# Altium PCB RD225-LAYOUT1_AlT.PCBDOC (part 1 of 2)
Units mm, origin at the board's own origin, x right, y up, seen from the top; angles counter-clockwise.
Board outline 85.6 x 53.98 mm, 2 copper layers (TOP, BOTTOM), stack 0 mm thick; 16 components, 11 nets, 48 pads, 0 vias.
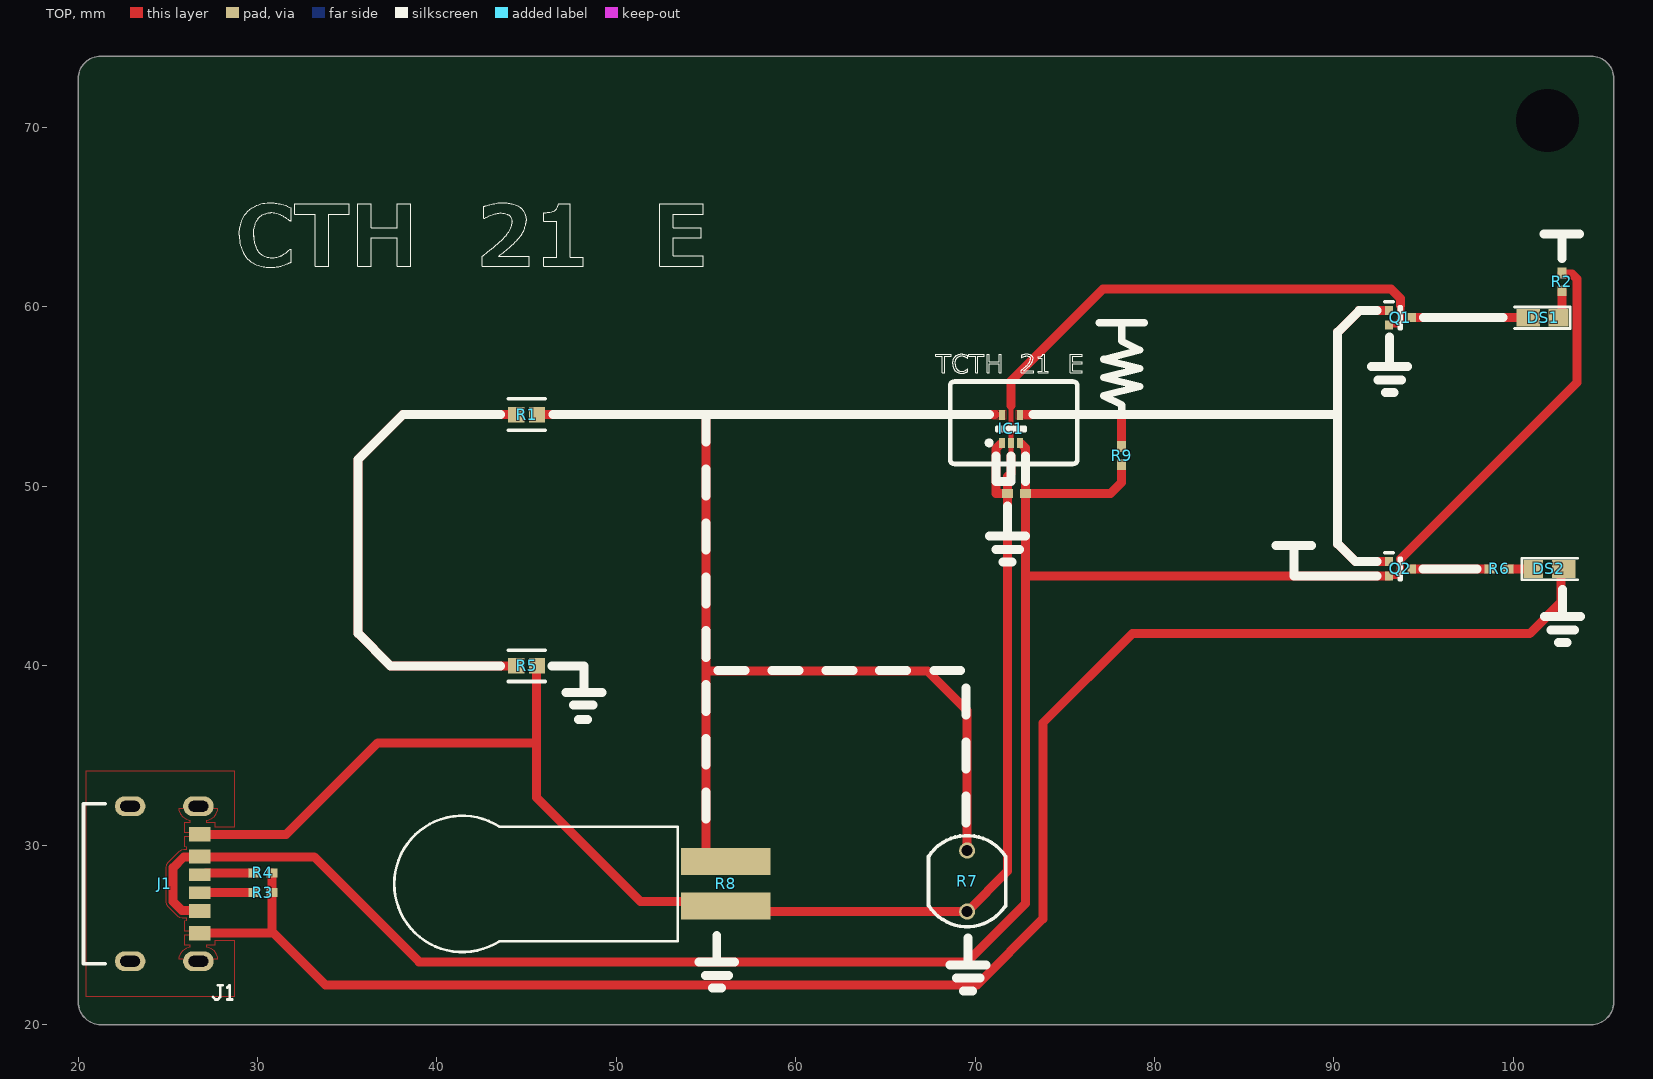
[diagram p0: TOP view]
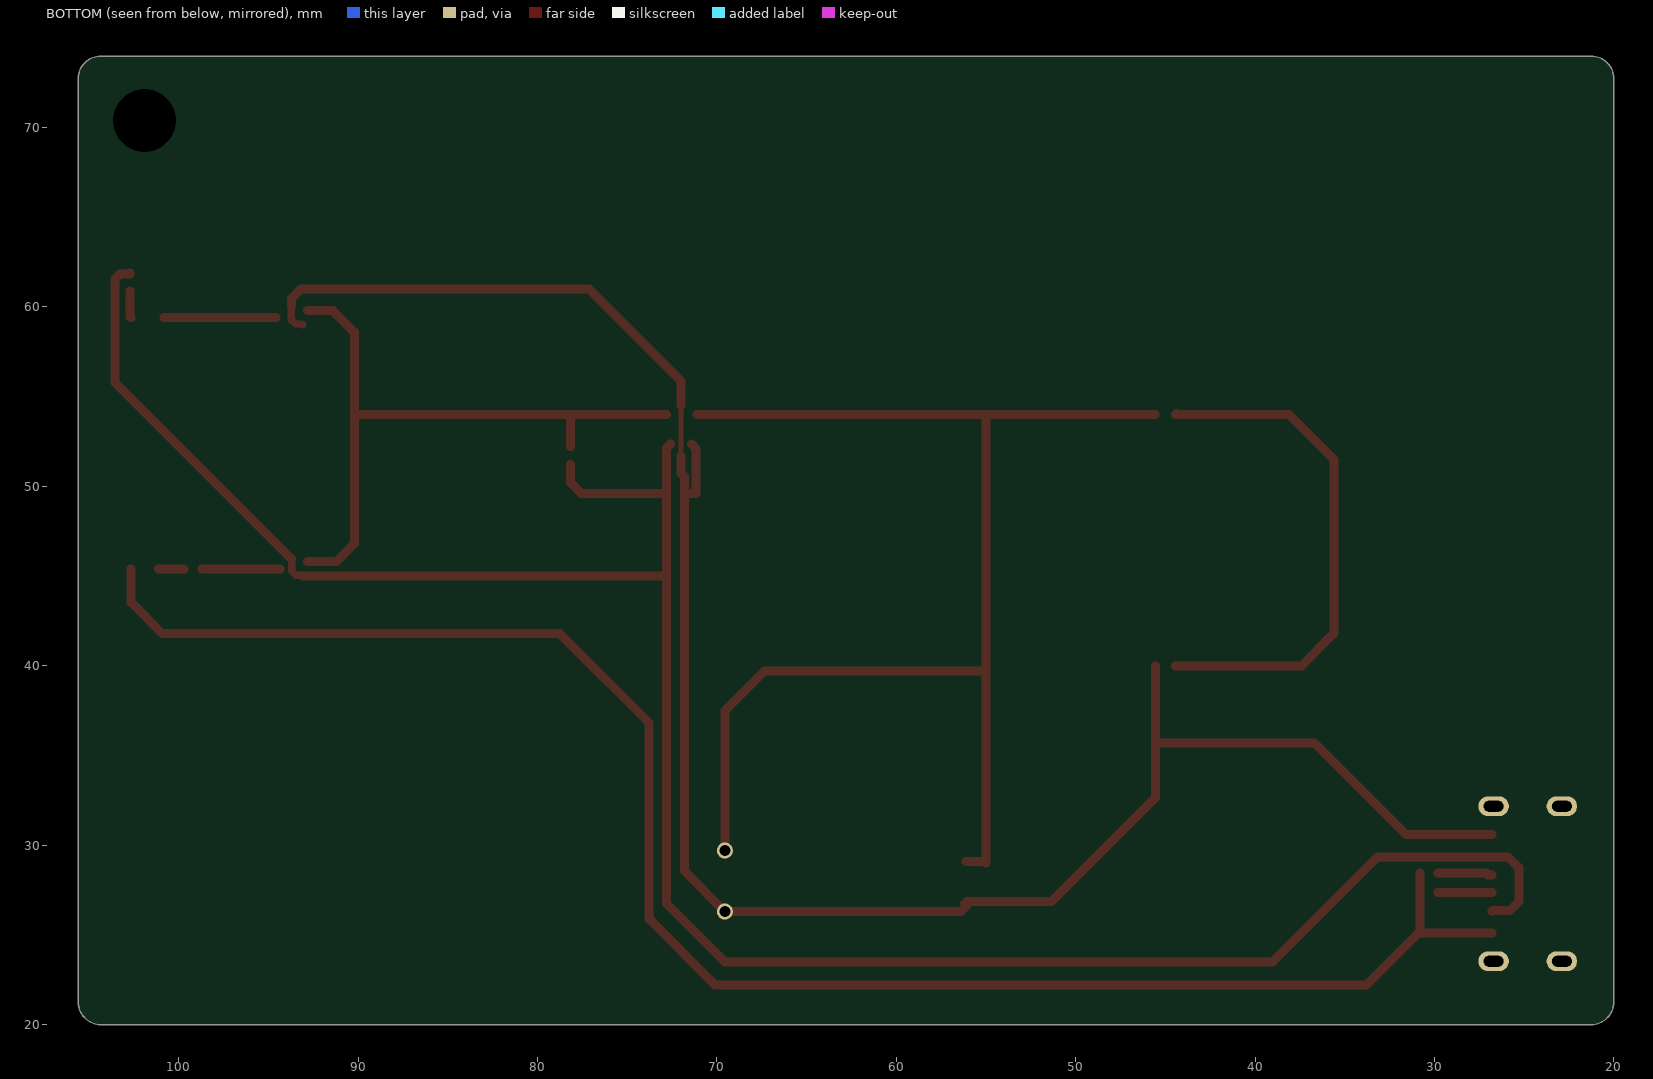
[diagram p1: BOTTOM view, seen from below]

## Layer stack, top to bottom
Top Solder: solder mask 0.0102, Solder Resist, Dk 3.5
TOP: signal copper (thickness not stored)
BOTTOM: signal copper (thickness not stored)
Bottom Solder: solder mask 0.0102, Solder Resist, Dk 3.5

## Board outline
21.145,20 20.9,20.049 20.668,20.145 20.46,20.284 20.284,20.46 20.145,20.668 20.049,20.9 20,21.145 20,72.835 20.049,73.08 20.145,73.312 20.284,73.52 20.46,73.696 20.668,73.835 20.9,73.931 21.145,73.98 104.455,73.98 104.7,73.931 104.932,73.835 105.14,73.696 105.316,73.52 105.455,73.312 105.551,73.08 105.6,72.835 105.6,21.145 105.551,20.9 105.455,20.668 105.316,20.46 105.14,20.284 104.932,20.145 104.7,20.049 104.455,20

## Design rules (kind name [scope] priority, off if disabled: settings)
AssemblyTestPointUsage [All] p0: scope1count=1 scope1_0_kind=Board scope1_0_value=Board scope2count=1 scope2_0_kind=Board scope2_0_value=Board commentlength=0
AssemblyTestpoint [All] p0: scope1count=1 scope1_0_kind=Board scope1_0_value=Board scope2count=1 scope2_0_kind=Board scope2_0_value=Board commentlength=0
Clearance [All] p0: scope1count=1 scope1_0_kind=Board scope1_0_value=Board scope2count=1 scope2_0_kind=Board scope2_0_value=Board commentlength=0 gap=0.001
Clearance [All] p1: gap=0.001 ignorepadtopadclearanceinfootprint=TRUE except(0.15: Arc-Arc Arc-Track Arc-SMDPad Arc-THPad Arc-Via Arc-Fill Arc-Poly Arc-Region Arc-Text Track-Track Track-SMDPad Track-THPad Track-Via Track-Fill Track-Poly Track-Region Track-Text SMDPad-SMDPad SMDPad-THPad SMDPad-Via SMDPad-Text THPad-THPad THPad-Via THPad-Text Via-Via Via-Fill Via-Poly Via-Region Via-Text Fill-Fill Fill-Poly Fill-Region Fill-Text Poly-Poly Poly-Region Poly-Text Region-Region Region-Text Text-Text; 0.2: SMDPad-Fill SMDPad-Poly SMDPad-Region THPad-Fill THPad-Poly THPad-Region; 0.3: Arc-Hole Track-Hole SMDPad-Hole THPad-Hole Via-Hole Fill-Hole Poly-Hole Region-Hole Text-Hole)
ComponentClearance [All] p0: scope1count=1 scope1_0_kind=Board scope1_0_value=Board scope2count=1 scope2_0_kind=Board scope2_0_value=Board commentlength=0 gap=0.254 collisioncheckmode=3
DiffPairsRouting [All] p0: scope1count=1 scope1_0_kind=Board scope1_0_value=Board scope2count=1 scope2_0_kind=Board scope2_0_value=Board commentlength=0
FabricationTestPointUsage [All] p0: scope1count=1 scope1_0_kind=Board scope1_0_value=Board scope2count=1 scope2_0_kind=Board scope2_0_value=Board commentlength=0 valid=0 allowmultiple=FALSE
FabricationTestpoint [All] p0: scope1count=1 scope1_0_kind=Board scope1_0_value=Board scope2count=1 scope2_0_kind=Board scope2_0_value=Board commentlength=0 side=3 testpointundercomponent=TRUE minsize=1.016 maxsize=2.54 preferedsize=1.524 minholesize=0 maxholesize=1.016 preferedholesize=0.813 testpointgrid=0.025
FanoutControl Fanout_Default [All] p0: scope1count=1 scope1_0_kind=Board scope1_0_value=Board scope2count=1 scope2_0_kind=Board scope2_0_value=Board commentlength=30 // Fanout_Default (Default Rule)
FanoutControl Fanout_Small [All] p0 off: scope1count=1 scope1_0_kind=Board scope1_0_value=Board scope2count=1 scope2_0_kind=Board scope2_0_value=Board commentlength=84 // Protel DXP Scope 1 Expression Was: (CompPinCount < 5)   Fanout_Small (Default Rule)
FanoutControl Fanout_SOIC [All] p0 off: scope1count=1 scope1_0_kind=Board scope1_0_value=Board scope2count=1 scope2_0_kind=Board scope2_0_value=Board commentlength=71 // Protel DXP Scope 1 Expression Was: IsSOIC   Fanout_SOIC (Default Rule)
FanoutControl Fanout_LCC [All] p0 off: scope1count=1 scope1_0_kind=Board scope1_0_value=Board scope2count=1 scope2_0_kind=Board scope2_0_value=Board commentlength=69 // Protel DXP Scope 1 Expression Was: IsLCC   Fanout_LCC (Default Rule)
FanoutControl Fanout_BGA [All] p0 off: scope1count=1 scope1_0_kind=Board scope1_0_value=Board scope2count=1 scope2_0_kind=Board scope2_0_value=Board commentlength=69 // Protel DXP Scope 1 Expression Was: IsBGA   Fanout_BGA (Default Rule)
Height [All] p0: scope1count=1 scope1_0_kind=Board scope1_0_value=Board scope2count=1 scope2_0_kind=Board scope2_0_value=Board commentlength=0
HoleSize [All] p0: scope1count=1 scope1_0_kind=Board scope1_0_value=Board scope2count=1 scope2_0_kind=Board scope2_0_value=Board commentlength=0 absolutevalues=TRUE maxlimit=100 minlimit=0.001 maxpercent=80.000 minpercent=20.000
HoleSize [All] p1: absolutevalues=TRUE maxlimit=100 minlimit=0.001 maxpercent=80.000 minpercent=20.000
HoleToHoleClearance [All] p0: scope1count=1 scope1_0_kind=Board scope1_0_value=Board scope2count=1 scope2_0_kind=Board scope2_0_value=Board commentlength=0
HoleToHoleClearance [All] p1: gap=0.4 allowstackedmicrovias=FALSE
LayerPairs [All] p0: scope1count=1 scope1_0_kind=Board scope1_0_value=Board scope2count=1 scope2_0_kind=Board scope2_0_value=Board commentlength=0 enforce=TRUE
MinimumSolderMaskSliver [All] p0: scope1count=1 scope1_0_kind=Board scope1_0_value=Board scope2count=1 scope2_0_kind=Board scope2_0_value=Board commentlength=0
MinimumSolderMaskSliver [All] p1: minsoldermaskwidth=0.1
NetAntennae [All] p0: scope1count=1 scope1_0_kind=Board scope1_0_value=Board scope2count=1 scope2_0_kind=Board scope2_0_value=Board commentlength=0
NetAntennae [All] p1: netantennaetolerance=100
PasteMaskExpansion [All] p0: scope1count=1 scope1_0_kind=Board scope1_0_value=Board scope2count=1 scope2_0_kind=Board scope2_0_value=Board commentlength=0 expansion=0
PlaneClearance [All] p0: scope1count=1 scope1_0_kind=Board scope1_0_value=Board scope2count=1 scope2_0_kind=Board scope2_0_value=Board commentlength=0 clearance=0.001
PlaneClearance [All] p1: clearance=0.001
PlaneConnect [All] p0: scope1count=1 scope1_0_kind=Board scope1_0_value=Board scope2count=1 scope2_0_kind=Board scope2_0_value=Board commentlength=0 planeconnectstyle=Direct reliefexpansion=0.508 reliefentries=4 reliefconductorwidth=0.254 reliefairgap=0.254
PlaneConnect [All] p1: planeconnectstyle=Direct reliefexpansion=0.508 reliefentries=4 reliefconductorwidth=0.254 reliefairgap=0.254
PolygonConnect [All] p0: scope1count=1 scope1_0_kind=Board scope1_0_value=Board scope2count=1 scope2_0_kind=Board scope2_0_value=Board commentlength=0 connectstyle=Direct reliefconductorwidth=0.254 reliefentries=4 polygonreliefangle="90 Angle"
PolygonConnect [All] p1: connectstyle=Direct reliefconductorwidth=0.254 reliefentries=4 polygonreliefangle="90 Angle" airgapwidth=0.254
RoutingCorners [All] p0: scope1count=1 scope1_0_kind=Board scope1_0_value=Board scope2count=1 scope2_0_kind=Board scope2_0_value=Board commentlength=0 cornerstyle=45-Degree minsetback=2.54 maxsetback=2.54
RoutingLayers [All] p0: scope1count=1 scope1_0_kind=Board scope1_0_value=Board scope2count=1 scope2_0_kind=Board scope2_0_value=Board commentlength=0 top layer=Automatic bottom layer=Automatic
RoutingPriority [All] p0: scope1count=1 scope1_0_kind=Board scope1_0_value=Board scope2count=1 scope2_0_kind=Board scope2_0_value=Board commentlength=0
RoutingTopology [All] p0: scope1count=1 scope1_0_kind=Board scope1_0_value=Board scope2count=1 scope2_0_kind=Board scope2_0_value=Board commentlength=0 topology=Shortest
RoutingVias [All] p0: scope1count=1 scope1_0_kind=Board scope1_0_value=Board scope2count=1 scope2_0_kind=Board scope2_0_value=Board commentlength=0 holewidth=0.1 width=0.1 viastyle="Through Hole" minholewidth=0.001 minwidth=0.001 maxholewidth=100 maxwidth=100
RoutingVias [All] p1: holewidth=0.1 width=0.1 viastyle="Through Hole" minholewidth=0.001 minwidth=0.001 maxholewidth=100 maxwidth=100
ShortCircuit [All] p0: scope1count=1 scope1_0_kind=Board scope1_0_value=Board scope2count=1 scope2_0_kind=Board scope2_0_value=Board commentlength=0 allowed=FALSE
ShortCircuit [All] p0: scope1count=1 scope1_0_kind=Board scope1_0_value=Board scope2count=1 scope2_0_kind=Board scope2_0_value=Board commentlength=0 allowed=FALSE
SilkToBoardRegionClearance [All] p0: scope1count=1 scope1_0_kind=Board scope1_0_value=Board scope2count=1 scope2_0_kind=Board scope2_0_value=Board commentlength=0
SilkToSilkClearance [All] p0: scope1count=1 scope1_0_kind=Board scope1_0_value=Board scope2count=1 scope2_0_kind=Board scope2_0_value=Board commentlength=0
SilkToSilkClearance [All] p1: silktosilkclearance=0.001
SilkToSolderMaskClearance [All] p0 off: scope1count=1 scope1_0_kind=Board scope1_0_value=Board scope2count=1 scope2_0_kind=Board scope2_0_value=Board commentlength=44 // Protel DXP Scope 1 Expression Was: IsPad
SilkToSolderMaskClearance [IsPad] p1: minsilkscreentomaskgap=0 clearancetoexposedcopper=TRUE
SolderMaskExpansion [All] p0: scope1count=1 scope1_0_kind=Board scope1_0_value=Board scope2count=1 scope2_0_kind=Board scope2_0_value=Board commentlength=0 expansion=0.001
SolderMaskExpansion [All] p1: expansion=0.001
UnRoutedNet [All] p0: scope1count=1 scope1_0_kind=Board scope1_0_value=Board scope2count=1 scope2_0_kind=Board scope2_0_value=Board commentlength=0
UnpouredPolygon [All] p0: scope1count=1 scope1_0_kind=Board scope1_0_value=Board scope2count=1 scope2_0_kind=Board scope2_0_value=Board commentlength=0
Width [All] p0: scope1count=1 scope1_0_kind=Board scope1_0_value=Board scope2count=1 scope2_0_kind=Board scope2_0_value=Board commentlength=0 maxlimit=1000 minlimit=2539.975 preferedwidth=0
Width [All] p1: maxlimit=1000 minlimit=2539.975 preferedwidth=0 toplayer_minwidth=0 bottomlayer_minwidth=0 minimp=50.000000 maximp=50.000000 favimp=50.000000
22 further rules are at their usual default settings.

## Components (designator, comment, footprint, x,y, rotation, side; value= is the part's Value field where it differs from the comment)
DS1 "1608_0603_-LED_-_Toshiba" 1608_0603_-LED_-_Toshiba 101.67,59.4 r180 top
DS2 "1608_0603_-LED_-_Toshiba" 1608_0603_-LED_-_Toshiba 101.96,45.4 r0 top
IC1 "TCTH021BE" TCTH021BE 72,53.2 r90 top
J1 "USB4125GFA0190" USB4125GFA0190 23.7,27.85 r270 top
Q1 "SOTFL40P120X55-3N" SOTFL40P120X55-3N 93.7,59.4 r0 top
Q2 "SOTFL40P120X55-3N" SOTFL40P120X55-3N 93.7,45.4 r0 top
R1 "FP-PRF18-PRG18-0_15-IPC_C" FP-PRF18-PRG18-0_15-IPC_C 45,54 r0 top
R2 "1005_0402_High_Density" 1005_0402_High_Density 102.7,61.4 r90 top
R3 "1005_0402_High_Density" 1005_0402_High_Density 30.3,27.35 r180 top
R4 "1005_0402_High_Density" 1005_0402_High_Density 30.3,28.45 r180 top
R5 "FP-PRF18-PRG18-0_15-IPC_C" FP-PRF18-PRG18-0_15-IPC_C 45,40 r180 top
R6 "1005_0402_High_Density" 1005_0402_High_Density 99.2,45.4 r180 top
R7 "PDV-P8104" PDV-P8104 69.55,29.7 r180 top
R8 "FSR_Model400_Short" FSR_Model400_Short 45.22,27.85 r90 top
R9 "1005_0402_High_Density" 1005_0402_High_Density 78.166,51.717 r90 top
? "1005_0402_High_Density" 1005_0402_High_Density 72.3,49.6 r0 top

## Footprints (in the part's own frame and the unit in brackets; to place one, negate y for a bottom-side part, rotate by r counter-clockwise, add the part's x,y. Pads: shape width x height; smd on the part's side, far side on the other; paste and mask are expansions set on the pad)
1005_0402_High_Density [mm] "KC00080BKP"
  rect 0.6x0.5 smd paste-0.803 mask+0: 1(-0.5,0) 2(0.5,0)
1608_0603_-LED_-_Toshiba [mm] "KC00080BKP"
  rect 1.1x1 smd paste-1.303 mask+0: 1(-0.85,0)
  rect 1.3x1 smd paste-1.503 mask+0: 2(0.85,0)
FP-PRF18-PRG18-0_15-IPC_C [mm] "KC00080BKP"
  rect 0.906x0.858 smd paste-0.906 mask+0: 1(-0.576,0) 2(0.576,0)
FSR_Model400_Short [mm] "KC00080BKP"
  rect 1.5x5 smd paste-5.203 mask+0: 1(-1.25,-10.87) 2(1.25,-10.88)
PDV-P8104 [mm] "KC00080BKP"
  round 0.9 / inner round 0 / far side round 0.9 hole 0.6 paste-1.103 mask+0: 1(0,0) 2(0,3.4)
SOTFL40P120X55-3N [mm] "KC00080BKP"
  rect 0.465x0.5 smd paste-0.703 mask+0: 1(-0.632,0.4) 2(-0.632,-0.4) 3(0.632,0)
TCTH021BE [mm] "KC00080BKP"
  rect 0.55x0.35 smd paste-0.753 mask+0: 1(-0.775,0.5) 2(-0.775,0) 3(-0.775,-0.5) 4(0.775,-0.5) 5(0.775,0.5)
USB4125GFA0190 [mm] "KC00080BKP"
  rect 0.7x1.2 smd paste-1.403 mask+0: A5(-0.5,3.08) B5(0.5,3.08)
  rect 0.76x1.2 smd paste-1.403 mask+0: A9(1.52,3.08) B9(-1.52,3.08)
  rect 0.8x1.2 smd paste-1.403 mask+0: A12(2.75,3.08) B12(-2.75,3.08)
  oval 1.1x1.7 / inner round 0 / far side oval 1.1x1.7 hole 0.6 slot 1.1 at 90 deg paste-1.903 mask+0: MH1(-4.32,3) MH2(-4.32,-0.8) MH3(4.32,-0.8) MH4(4.32,3)

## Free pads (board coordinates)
  round 0.5 smd paste-0.5 mask+0: ""(29.75,27.35)
  round 0.3 smd paste-0.3 mask+0: ""(72,51.7)
  round 0 hole 3.5 unplated paste-3.5 mask+0: ""(101.9,70.4)

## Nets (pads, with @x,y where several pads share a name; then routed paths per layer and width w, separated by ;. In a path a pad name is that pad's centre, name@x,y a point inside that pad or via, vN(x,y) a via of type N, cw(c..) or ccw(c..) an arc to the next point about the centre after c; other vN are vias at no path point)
GND: ?.1 DS2.2 IC1.1 IC1.2 J1.A12 J1.B12 J1.MH1 J1.MH2 J1.MH3 J1.MH4 pad.@72,51.7 Q1.2 R3.1 R4.1 R5.1 R7.2 R8.1 | length 212.7
  TOP w0.3: 30.8,25.2 30.9,25.1 ; pad.@72,51.7 IC1.2@72,52.425 72,54.52
  TOP w0.4: Q1.2@93.068,59 93.068,59.017 93.1,59.05 93.486,59.05 93.72,59.284 93.72,60.07
  TOP w0.5: J1.A12@26.78,25.1 30.9,25.1 33.8,22.2 70.09,22.2 73.78,25.89 73.78,36.81 78.76,41.79 100.91,41.79 102.65,43.53 DS2.2@102.65,45.4 ; J1.B12@26.78,30.6 31.6,30.6 36.7,35.7 45.552,35.7 ; 30.8,25.2 R3.1@30.8,27.35 R4.1@30.8,28.45 ; R5.1@45.552,40 45.552,35.7 ; R8.1@56.09,26.6 56.39,26.3 R7.2@69.55,26.3 71.8,28.55 ?.1@71.8,49.6 ; R8.1@56.205,26.715 56.07,26.85 51.35,26.85 45.55,32.65 45.552,32.652 45.552,35.7 ; IC1.1@71.425,52.369 71.15,52.094 71.15,49.6 ?.1@71.8,49.6 ; pad.@72,51.7 72,50.74 71.8,50.54 ?.1@71.8,49.6 ; 72,54.52 72,55.88 77.12,61 93.19,61 93.72,60.47 93.72,60.07
NetDS1_1: DS1.1 R2.1 | length 1.5
  TOP w0.5: DS1.1@102.65,59.4 102.7,59.45 R2.1@102.7,60.9
NetDS1_2: DS1.2 Q1.3 | length 6.2
  TOP w0.5: 94.58,59.4 DS1.2@100.82,59.4
NetDS2_1: DS2.1 R6.1 | length 1.4
  TOP w0.5: R6.1@99.7,45.4 99.81,45.4 DS2.1@101.11,45.4
NetJ1_A5: J1.A5 R4.2 | length 3.1
  TOP w0.5: J1.A5@26.78,28.35 27.03,28.35 27.13,28.45 R4.2@29.8,28.45
NetJ1_B5: J1.B5 pad.@29.75,27.35 R3.2 | length 3
  TOP w0.5: J1.B5@26.78,27.35 pad.@29.75,27.35 R3.2@29.8,27.35
NetQ2_3: Q2.3 R6.2 | length 4.3
  TOP w0.5: Q2.3@94.36,45.4 R6.2@98.7,45.4
NetR1_1: R1.1 R5.2 | length 29.2
  TOP w0.5: R5.2@44.424,40 37.4,40 35.6,41.8 35.6,51.5 38.1,54 44.314,54 44.369,54.055 R1.1@44.424,54
PTCGOOD: IC1.4 Q1.1 Q2.1 R9.2 | length 37.1
  TOP w0.5: 72.8,54 90.2,54 ; R9.2@78.166,52.216 78.166,54 ; 92.82,59.8 91.4,59.8 90.2,58.6 90.2,54 ; 92.83,45.8 91.2,45.8 90.2,46.8 90.2,54
PTCO: IC1.5 R1.2 R7.1 R8.2 | length 74.9
  TOP w0.5: R1.2@45.576,54 55,54 ; 55.05,39.7 67.35,39.7 69.55,37.5 R7.1@69.55,29.7 ; R8.2@56.1,29.1 55.1,29.1 55,29 55,54 ; 71.1,54 55,54
VP_5R0_VBUS: ?.2 IC1.3 J1.A9 J1.B9 Q2.2 R2.2 R9.1 | length 129.9
  TOP w0.4: Q2.2@93.068,45 93.068,45.017 93.1,45.05 93.456,45.05 93.69,45.284 93.69,45.93 93.72,45.96
  TOP w0.5: J1.A9@26.78,26.33 26.76,26.35 25.8,26.35 25.3,26.85 25.3,28.75 25.9,29.35 26.78,29.35 33.15,29.35 39.01,23.49 69.55,23.49 72.8,26.74 72.8,45 ; IC1.3@72.575,52.369 72.8,52.144 ?.2@72.8,49.6 ; R9.1@78.166,51.216 78.166,50.226 77.54,49.6 ?.2@72.8,49.6 ; Q2.2@93.068,45 72.8,45 ; 93.72,45.96 103.55,55.79 103.55,61.557 103.257,61.85 102.7,61.85 R2.2@102.7,61.9 ; 72.8,45 ?.2@72.8,49.6

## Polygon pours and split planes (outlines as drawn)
PTCGOOD on TOP "TOP3" (solid, pour order 4): 72.3,53.75 72.3,54.25 73.1,54.25 73.1,53.75
PTCO on TOP "TOP2" (solid, pour order 3): 71,53.75 71,54.25 71.7,54.25 71.7,53.75
GND on TOP "TOP1" (solid, pour order 2): 71 vertices, not listed, extent 20.45,21.55 28.7,34.15
no net on Top Overlay "TOPOVERLAY345" (solid, pour order 0): 125 vertices, not listed, extent 81.109,57.14 81.821,58.222
no net on Top Overlay "TOPOVERLAY344" (solid, pour order 0): 109 vertices, not listed, extent 74.349,56.321 75.124,57.362
no net on Top Overlay "TOPOVERLAY343" (solid, pour order 0): 125 vertices, not listed, extent 71.668,56.3 72.379,57.382
no net on Top Overlay "TOPOVERLAY342" (solid, pour order 0): 124 vertices, not listed, extent 39.193,62.2 41.933,65.814
no net on Top Overlay "TOPOVERLAY341" (solid, pour order 0): 98 vertices, not listed, extent 48.974,62.271 51.838,65.747
no net on Top Overlay "TOPOVERLAY340" (solid, pour order 0): 82.022,57.161 82.022,58.248 82.143,58.248 82.143,57.558 82.509,57.942 82.661,57.942 82.306,57.582 82.689,57.161 82.528,57.161 82.216,57.506 82.143,57.435 82.143,57.161
no net on Top Overlay "TOPOVERLAY339" (solid, pour order 0): 243 vertices, not listed, extent 82.744,57.161 83.752,58.223
no net on Top Overlay "TOPOVERLAY338" (solid, pour order 0): 32 vertices, not listed, extent 80.33,57.161 80.885,58.205
no net on Top Overlay "TOPOVERLAY337" (solid, pour order 0): 75.301,57.362 75.979,57.362 75.979,57.25 75.43,57.25 75.43,56.947 75.965,56.947 75.965,56.834 75.43,56.834 75.43,56.433 75.979,56.433 75.979,56.321 75.301,56.321
no net on Top Overlay "TOPOVERLAY336" (solid, pour order 0): 32 vertices, not listed, extent 73.526,56.321 74.08,57.365
no net on Top Overlay "TOPOVERLAY335" (solid, pour order 0): 169 vertices, not listed, extent 72.563,56.321 73.26,57.383
no net on Top Overlay "TOPOVERLAY334" (solid, pour order 0): 202 vertices, not listed, extent 68.748,56.303 69.59,57.38
no net on Top Overlay "TOPOVERLAY333" (solid, pour order 0): 70.661,57.362 70.79,57.362 70.79,56.947 71.329,56.947 71.329,57.362 71.457,57.362 71.457,56.321 71.329,56.321 71.329,56.835 70.79,56.835 70.79,56.321 70.661,56.321
no net on Top Overlay "TOPOVERLAY332" (solid, pour order 0): 68.169,57.25 67.8,57.25 67.8,57.362 68.667,57.362 68.667,57.25 68.297,57.25 68.297,56.321 68.169,56.321
no net on Top Overlay "TOPOVERLAY331" (solid, pour order 0): 70.019,57.25 69.65,57.25 69.65,57.362 70.517,57.362 70.517,57.25 70.148,57.25 70.148,56.321 70.019,56.321
no net on Top Overlay "TOPOVERLAY330" (solid, pour order 0): 52.431,65.747 54.852,65.747 54.852,65.169 53.184,65.169 53.184,64.427 54.733,64.427 54.733,63.853 53.184,63.853 53.184,62.845 54.852,62.845 54.852,62.271 52.431,62.271
no net on Top Overlay "TOPOVERLAY329" (solid, pour order 0): 32 vertices, not listed, extent 45.949,62.271 48.161,65.754
no net on Top Overlay "TOPOVERLAY328" (solid, pour order 0): 154 vertices, not listed, extent 42.511,62.271 45.131,65.814
no net on Top Overlay "TOPOVERLAY327" (solid, pour order 0): 207 vertices, not listed, extent 28.977,62.204 31.886,65.814
no net on Top Overlay "TOPOVERLAY326" (solid, pour order 0): 35.571,65.747 36.332,65.747 36.332,64.423 37.791,64.423 37.791,65.747 38.552,65.747 38.552,62.271 37.791,62.271 37.791,63.853 36.332,63.853 36.332,62.271 35.571,62.271
no net on Top Overlay "TOPOVERLAY325" (solid, pour order 0): 33.217,65.169 32.073,65.169 32.073,65.747 35.118,65.747 35.118,65.169 33.978,65.169 33.978,62.271 33.217,62.271
no net on Top Overlay "TOPOVERLAY324" (solid, pour order 0): 26.843,62.271 26.843,65.169 25.7,65.169 25.7,65.747 28.744,65.747 28.744,65.169 27.604,65.169 27.604,62.271
no net on Top Overlay "TOPOVERLAY323" (solid, pour order 0): 49 vertices, not listed, extent 78.806,51.368 79.406,52.102
no net on Top Overlay "TOPOVERLAY322" (solid, pour order 0): 181 vertices, not listed, extent 79.571,51.331 80.085,52.094
no net on Top Overlay "TOPOVERLAY321" (solid, pour order 0): 162 vertices, not listed, extent 104.186,60.925 104.677,61.675
no net on Top Overlay "TOPOVERLAY320" (solid, pour order 0): 49 vertices, not listed, extent 103.523,60.925 104.124,61.66
no net on Top Overlay "TOPOVERLAY319" (solid, pour order 0): 269 vertices, not listed, extent 101.947,46.319 102.489,47.079
no net on Top Overlay "TOPOVERLAY318" (solid, pour order 0): 75 vertices, not listed, extent 101.233,46.332 101.846,47.066
no net on Top Overlay "TOPOVERLAY317" (solid, pour order 0): 163 vertices, not listed, extent 102.596,46.332 103.087,47.082
no net on Top Overlay "TOPOVERLAY316" (solid, pour order 0): 270 vertices, not listed, extent 101.377,57.52 101.919,58.28
no net on Top Overlay "TOPOVERLAY315" (solid, pour order 0): 75 vertices, not listed, extent 100.664,57.533 101.277,58.267
no net on Top Overlay "TOPOVERLAY314" (solid, pour order 0): 31 vertices, not listed, extent 102.085,57.533 102.477,58.27
no net on Top Overlay "TOPOVERLAY313" (solid, pour order 0): 101.091,64.512 100.51,65.984 100.703,65.984 101.18,64.76 101.654,65.984 101.84,65.984 101.257,64.512
no net on Top Overlay "TOPOVERLAY312" (solid, pour order 0): 75 vertices, not listed, extent 102.037,64.512 103.264,65.984
no net on Top Overlay "TOPOVERLAY311" (solid, pour order 0): 75 vertices, not listed, extent 103.534,64.512 104.761,65.984
no net on Top Overlay "TOPOVERLAY310" (solid, pour order 0): 181 vertices, not listed, extent 99.269,46.019 99.783,46.782
no net on Top Overlay "TOPOVERLAY309" (solid, pour order 0): 49 vertices, not listed, extent 98.618,46.034 99.218,46.768
no net on Top Overlay "TOPOVERLAY308" (solid, pour order 0): 75 vertices, not listed, extent 94.75,59.95 95.716,61.108
no net on Top Overlay "TOPOVERLAY307" (solid, pour order 0): 75 vertices, not listed, extent 94.5,43.65 95.466,44.808
no net on Top Overlay "TOPOVERLAY306" (solid, pour order 0): 31 vertices, not listed, extent 93.927,60.821 94.318,61.558
no net on Top Overlay "TOPOVERLAY305" (solid, pour order 0): 190 vertices, not listed, extent 93.082,60.63 93.767,61.571
no net on Top Overlay "TOPOVERLAY304" (solid, pour order 0): 163 vertices, not listed, extent 93.847,46.821 94.339,47.571
no net on Top Overlay "TOPOVERLAY303" (solid, pour order 0): 190 vertices, not listed, extent 93.061,46.63 93.746,47.571
no net on Top Overlay "TOPOVERLAY302" (solid, pour order 0): 270 vertices, not listed, extent 91.65,43.3 92.505,44.498
no net on Top Overlay "TOPOVERLAY301" (solid, pour order 0): 270 vertices, not listed, extent 91.55,58 92.405,59.198
no net on Top Overlay "TOPOVERLAY300" (solid, pour order 0): 191 vertices, not listed, extent 91.45,46.25 92.441,47.45
no net on Top Overlay "TOPOVERLAY299" (solid, pour order 0): 191 vertices, not listed, extent 91.4,60.2 92.391,61.4
no net on Top Overlay "TOPOVERLAY298" (solid, pour order 0): 92.331,62.665 92.331,62.795 92.811,62.795 92.811,62.665
no net on Top Overlay "TOPOVERLAY297" (solid, pour order 0): 91.2,62.224 91.2,63.382 91.399,63.382 91.95,62.431 91.95,63.382 92.084,63.382 92.084,62.224 91.917,62.224 91.334,63.228 91.334,62.224
no net on Top Overlay "TOPOVERLAY296" (solid, pour order 0): 95.366,62.224 95.366,63.382 95.55,63.382 95.878,62.715 96.206,63.382 96.39,63.382 96.39,62.224 96.247,62.224 96.247,63.218 95.913,62.539 95.834,62.539 95.5,63.218 95.5,62.224
no net on Top Overlay "TOPOVERLAY295" (solid, pour order 0): 270 vertices, not listed, extent 97.821,62.204 98.676,63.402
no net on Top Overlay "TOPOVERLAY294" (solid, pour order 0): 176 vertices, not listed, extent 92.985,62.204 93.679,63.114
no net on Top Overlay "TOPOVERLAY293" (solid, pour order 0): 98.874,62.224 98.874,63.382 99.605,63.382 99.605,63.257 99.018,63.257 99.018,62.911 99.54,62.911 99.54,62.786 99.018,62.786 99.018,62.224
no net on Top Overlay "TOPOVERLAY292" (solid, pour order 0): 88 vertices, not listed, extent 93.847,62.224 94.565,63.433
no net on Top Overlay "TOPOVERLAY291" (solid, pour order 0): 99.774,62.224 99.774,63.382 100.529,63.382 100.529,63.257 99.918,63.257 99.918,62.92 100.514,62.92 100.514,62.795 99.918,62.795 99.918,62.347 100.529,62.347 100.529,62.224
no net on Top Overlay "TOPOVERLAY290" (solid, pour order 0): 123 vertices, not listed, extent 96.605,62.2 97.662,63.406
no net on Top Overlay "TOPOVERLAY289" (solid, pour order 0): 101.034,62.224 101.034,63.257 100.623,63.257 100.623,63.382 101.587,63.382 101.587,63.257 101.176,63.257 101.176,62.224
no net on Top Overlay "TOPOVERLAY288" (solid, pour order 0): 95.138,48.124 95.138,49.282 95.321,49.282 95.649,48.615 95.978,49.282 96.161,49.282 96.161,48.124 96.019,48.124 96.019,49.118 95.684,48.439 95.605,48.439 95.271,49.118 95.271,48.124
no net on Top Overlay "TOPOVERLAY287" (solid, pour order 0): 92.102,48.565 92.102,48.695 92.582,48.695 92.582,48.565
no net on Top Overlay "TOPOVERLAY286" (solid, pour order 0): 123 vertices, not listed, extent 96.376,48.1 97.433,49.306
no net on Top Overlay "TOPOVERLAY285" (solid, pour order 0): 270 vertices, not listed, extent 97.592,48.104 98.447,49.302
no net on Top Overlay "TOPOVERLAY284" (solid, pour order 0): 176 vertices, not listed, extent 92.756,48.104 93.451,49.014
no net on Top Overlay "TOPOVERLAY283" (solid, pour order 0): 98.646,48.124 98.646,49.282 99.377,49.282 99.377,49.157 98.789,49.157 98.789,48.811 99.312,48.811 99.312,48.686 98.789,48.686 98.789,48.124
no net on Top Overlay "TOPOVERLAY282" (solid, pour order 0): 88 vertices, not listed, extent 93.618,48.124 94.337,49.333
no net on Top Overlay "TOPOVERLAY281" (solid, pour order 0): 99.545,48.124 99.545,49.282 100.3,49.282 100.3,49.157 99.689,49.157 99.689,48.82 100.285,48.82 100.285,48.695 99.689,48.695 99.689,48.247 100.3,48.247 100.3,48.124
no net on Top Overlay "TOPOVERLAY280" (solid, pour order 0): 65 vertices, not listed, extent 91.2,48.124 91.959,49.282
no net on Top Overlay "TOPOVERLAY279" (solid, pour order 0): 100.805,48.124 100.805,49.157 100.394,49.157 100.394,49.282 101.359,49.282 101.359,49.157 100.947,49.157 100.947,48.124
no net on Top Overlay "TOPOVERLAY278" (solid, pour order 0): 86.149,47.156 85.568,48.628 85.762,48.628 86.238,47.404 86.712,48.628 86.898,48.628 86.316,47.156
no net on Top Overlay "TOPOVERLAY277" (solid, pour order 0): 75 vertices, not listed, extent 87.095,47.156 88.322,48.628
no net on Top Overlay "TOPOVERLAY276" (solid, pour order 0): 75 vertices, not listed, extent 88.592,47.156 89.819,48.628
no net on Top Overlay "TOPOVERLAY275" (solid, pour order 0): 123 vertices, not listed, extent 85.329,54.55 86.673,56.082
no net on Top Overlay "TOPOVERLAY274" (solid, pour order 0): 191 vertices, not listed, extent 83.874,54.553 85.133,56.077
no net on Top Overlay "TOPOVERLAY273" (solid, pour order 0): 197 vertices, not listed, extent 82.529,54.555 83.72,56.077
no net on Top Overlay "TOPOVERLAY272" (solid, pour order 0): 123 vertices, not listed, extent 86.853,54.55 88.197,56.082
no net on Top Overlay "TOPOVERLAY271" (solid, pour order 0): 75 vertices, not listed, extent 88.466,54.58 89.694,56.052
no net on Top Overlay "TOPOVERLAY270" (solid, pour order 0): 81.712,54.58 81.712,55.893 81.189,55.893 81.189,56.052 82.415,56.052 82.415,55.893 81.893,55.893 81.893,54.58
no net on Top Overlay "TOPOVERLAY269" (solid, pour order 0): 65 vertices, not listed, extent 80.154,54.58 81.118,56.052
no net on Top Overlay "TOPOVERLAY268" (solid, pour order 0): 76.7,59.509 76.119,60.981 76.313,60.981 76.789,59.757 77.263,60.981 77.449,60.981 76.867,59.509
no net on Top Overlay "TOPOVERLAY267" (solid, pour order 0): 75 vertices, not listed, extent 77.646,59.509 78.873,60.981
no net on Top Overlay "TOPOVERLAY266" (solid, pour order 0): 75 vertices, not listed, extent 79.143,59.509 80.37,60.981
no net on Top Overlay "TOPOVERLAY265" (solid, pour order 0): 197 vertices, not listed, extent 73.921,52.12 74.515,52.88
no net on Top Overlay "TOPOVERLAY264" (solid, pour order 0): 31 vertices, not listed, extent 74.676,52.133 75.068,52.87
no net on Top Overlay "TOPOVERLAY263" (solid, pour order 0): 73.533,52.133 73.533,52.2 73.628,52.2 73.628,52.799 73.533,52.799 73.533,52.867 73.815,52.867 73.815,52.799 73.72,52.799 73.72,52.2 73.815,52.2 73.815,52.133
no net on Top Overlay "TOPOVERLAY262" (solid, pour order 0): 91.088,26.568 91.055,27.833 91.298,27.833 91.268,26.568
no net on Top Overlay "TOPOVERLAY261" (solid, pour order 0): 86 vertices, not listed, extent 74.737,26.06 75.815,27.398
no net on Top Overlay "TOPOVERLAY260" (solid, pour order 0): 78.462,27.659 78.462,27.869 78.69,27.869 78.69,27.659
no net on Top Overlay "TOPOVERLAY259" (solid, pour order 0): 51 vertices, not listed, extent 87.785,26.096 88.586,27.398
no net on Top Overlay "TOPOVERLAY258" (solid, pour order 0): 159 vertices, not listed, extent 76.207,26.096 78.09,27.434
no net on Top Overlay "TOPOVERLAY257" (solid, pour order 0): 87 vertices, not listed, extent 79.073,26.096 80.151,27.434
no net on Top Overlay "TOPOVERLAY256" (solid, pour order 0): 91.058,26.096 91.058,26.337 91.295,26.337 91.295,26.096
no net on Top Overlay "TOPOVERLAY255" (solid, pour order 0): 72 vertices, not listed, extent 81.763,26.071 82.571,27.773
no net on Top Overlay "TOPOVERLAY254" (solid, pour order 0): 72.54,26.096 72.54,26.255 72.767,26.255 72.767,27.672 72.54,27.672 72.54,27.833 73.209,27.833 73.209,27.672 72.982,27.672 72.982,26.255 73.209,26.255 73.209,26.096
no net on Top Overlay "TOPOVERLAY253" (solid, pour order 0): 153 vertices, not listed, extent 88.665,26.066 89.834,27.434
no net on Top Overlay "TOPOVERLAY252" (solid, pour order 0): 153 vertices, not listed, extent 82.702,26.066 83.871,27.434
no net on Top Overlay "TOPOVERLAY251" (solid, pour order 0): 153 vertices, not listed, extent 86.327,26.066 87.497,27.434
no net on Top Overlay "TOPOVERLAY250" (solid, pour order 0): 162 vertices, not listed, extent 80.434,26.06 81.521,27.428
no net on Top Overlay "TOPOVERLAY249" (solid, pour order 0): 88 vertices, not listed, extent 84.962,26.096 86.04,27.91
no net on Top Overlay "TOPOVERLAY248" (solid, pour order 0): 78.475,26.096 78.475,27.398 78.679,27.398 78.679,26.096
no net on Top Overlay "TOPOVERLAY247" (solid, pour order 0): 73.548,26.096 73.548,27.91 73.753,27.91 73.753,26.096
no net on Top Overlay "TOPOVERLAY246" (solid, pour order 0): 74.148,26.096 74.148,27.91 74.353,27.91 74.353,26.096
no net on Top Overlay "TOPOVERLAY245" (solid, pour order 0): 197 vertices, not listed, extent 69.727,49.22 70.321,49.98
no net on Top Overlay "TOPOVERLAY244" (solid, pour order 0): 31 vertices, not listed, extent 70.482,49.233 70.873,49.97
no net on Top Overlay "TOPOVERLAY243" (solid, pour order 0): 67.15,30.133 67.502,30.788 67.081,30.788 67.081,30.868 67.578,30.868 67.578,30.765 67.249,30.133
no net on Top Overlay "TOPOVERLAY242" (solid, pour order 0): 49 vertices, not listed, extent 66.422,30.133 67.023,30.868
no net on Top Overlay "TOPOVERLAY241" (solid, pour order 0): 123 vertices, not listed, extent 66.62,54.5 67.963,56.032
no net on Top Overlay "TOPOVERLAY240" (solid, pour order 0): 197 vertices, not listed, extent 65.275,54.505 66.466,56.027
no net on Top Overlay "TOPOVERLAY239" (solid, pour order 0): 64.457,54.53 64.457,55.843 63.935,55.843 63.935,56.002 65.161,56.002 65.161,55.843 64.638,55.843 64.638,54.53
no net on Top Overlay "TOPOVERLAY238" (solid, pour order 0): 65 vertices, not listed, extent 62.9,54.53 63.864,56.002
no net on Top Overlay "TOPOVERLAY237" (solid, pour order 0): 184 vertices, not listed, extent 52.364,31.617 52.88,32.384
no net on Top Overlay "TOPOVERLAY236" (solid, pour order 0): 49 vertices, not listed, extent 51.72,31.633 52.321,32.368
no net on Top Overlay "TOPOVERLAY235" (solid, pour order 0): 31 vertices, not listed, extent 45.165,55.332 45.557,56.069
no net on Top Overlay "TOPOVERLAY234" (solid, pour order 0): 49 vertices, not listed, extent 44.444,55.332 45.045,56.066
no net on Top Overlay "TOPOVERLAY233" (solid, pour order 0): 160 vertices, not listed, extent 45.101,37.825 45.574,38.575
no net on Top Overlay "TOPOVERLAY232" (solid, pour order 0): 49 vertices, not listed, extent 44.426,37.84 45.027,38.575
no net on Top Overlay "TOPOVERLAY231" (solid, pour order 0): 88 vertices, not listed, extent 44.4,49.5 45.343,51.815
no net on Top Overlay "TOPOVERLAY230" (solid, pour order 0): 86 vertices, not listed, extent 44.4,42 45.343,44.315
no net on Top Overlay "TOPOVERLAY229" (solid, pour order 0): 197 vertices, not listed, extent 45.32,36.25 46.257,37.448
no net on Top Overlay "TOPOVERLAY228" (solid, pour order 0): 163 vertices, not listed, extent 46.418,36.27 47.193,37.452
no net on Top Overlay "TOPOVERLAY227" (solid, pour order 0): 65 vertices, not listed, extent 43.45,36.27 44.209,37.428
no net on Top Overlay "TOPOVERLAY226" (solid, pour order 0): 44.676,36.27 44.676,37.303 44.265,37.303 44.265,37.428 45.23,37.428 45.23,37.303 44.818,37.303 44.818,36.27
no net on Top Overlay "TOPOVERLAY225" (solid, pour order 0): 197 vertices, not listed, extent 45.22,56.55 46.157,57.748
no net on Top Overlay "TOPOVERLAY224" (solid, pour order 0): 31 vertices, not listed, extent 46.41,56.57 47.028,57.732
no net on Top Overlay "TOPOVERLAY223" (solid, pour order 0): 65 vertices, not listed, extent 43.35,56.57 44.109,57.728
no net on Top Overlay "TOPOVERLAY222" (solid, pour order 0): 44.576,56.57 44.576,57.603 44.165,57.603 44.165,57.728 45.13,57.728 45.13,57.603 44.718,57.603 44.718,56.57
no net on Top Overlay "TOPOVERLAY221" (solid, pour order 0): 238 vertices, not listed, extent 42.787,21.4 43.786,22.763
no net on Top Overlay "TOPOVERLAY220" (solid, pour order 0): 153 vertices, not listed, extent 41.42,21.4 42.59,22.768
no net on Top Overlay "TOPOVERLAY219" (solid, pour order 0): 238 vertices, not listed, extent 43.964,21.4 44.963,22.763
no net on Top Overlay "TOPOVERLAY218" (solid, pour order 0): 51 vertices, not listed, extent 48.858,21.43 49.659,22.733
no net on Top Overlay "TOPOVERLAY217" (solid, pour order 0): 51 vertices, not listed, extent 40.541,21.43 41.341,22.733
no net on Top Overlay "TOPOVERLAY216" (solid, pour order 0): 153 vertices, not listed, extent 47.4,21.4 48.569,22.768
no net on Top Overlay "TOPOVERLAY215" (solid, pour order 0): 52.131,21.43 52.131,21.672 52.367,21.672 52.367,21.43
no net on Top Overlay "TOPOVERLAY214" (solid, pour order 0): 88 vertices, not listed, extent 46.035,21.43 47.113,23.245
no net on Top Overlay "TOPOVERLAY213" (solid, pour order 0): 52.161,21.902 52.127,23.168 52.371,23.168 52.341,21.902
no net on Top Overlay "TOPOVERLAY212" (solid, pour order 0): 153 vertices, not listed, extent 49.737,21.4 50.907,22.768
no net on Top Overlay "TOPOVERLAY211" (solid, pour order 0): 65 vertices, not listed, extent 39.15,21.43 40.288,23.168
no net on Top Overlay "TOPOVERLAY210" (solid, pour order 0): 153 vertices, not listed, extent 47.242,46.107 48.802,47.932
no net on Top Overlay "TOPOVERLAY209" (solid, pour order 0): 153 vertices, not listed, extent 50.359,46.107 51.919,47.932
no net on Top Overlay "TOPOVERLAY208" (solid, pour order 0): 153 vertices, not listed, extent 39.389,46.107 40.949,47.932
no net on Top Overlay "TOPOVERLAY207" (solid, pour order 0): 51 vertices, not listed, extent 49.187,46.147 50.254,47.885
no net on Top Overlay "TOPOVERLAY206" (solid, pour order 0): 37.2,46.147 37.2,48.464 37.487,48.464 37.487,47.54 38.687,47.54 38.687,48.464 38.972,48.464 38.972,46.147 38.687,46.147 38.687,47.292 37.487,47.292 37.487,46.147
no net on Top Overlay "TOPOVERLAY205" (solid, pour order 0): 88 vertices, not listed, extent 45.423,46.147 46.86,48.567
no net on Top Overlay "TOPOVERLAY204" (solid, pour order 0): 162 vertices, not listed, extent 41.201,46.1 42.651,47.925
no net on Top Overlay "TOPOVERLAY203" (solid, pour order 0): 53.551,46.147 53.551,46.47 53.866,46.47 53.866,46.147
no net on Top Overlay "TOPOVERLAY202" (solid, pour order 0): 53.591,46.777 53.546,48.464 53.871,48.464 53.831,46.777
no net on Top Overlay "TOPOVERLAY201" (solid, pour order 0): 72 vertices, not listed, extent 42.974,46.115 44.051,48.384
no net on Top Overlay "TOPOVERLAY200" (solid, pour order 0): 252 vertices, not listed, extent 32.194,26.968 32.672,27.732
no net on Top Overlay "TOPOVERLAY199" (solid, pour order 0): 49 vertices, not listed, extent 31.528,26.983 32.129,27.717
no net on Top Overlay "TOPOVERLAY198" (solid, pour order 0): 49 vertices, not listed, extent 31.515,28.083 32.116,28.818
no net on Top Overlay "TOPOVERLAY197" (solid, pour order 0): 32.49,28.083 32.49,28.295 32.137,28.295 32.137,28.397 32.494,28.818 32.578,28.818 32.578,28.367 32.685,28.367 32.685,28.295 32.578,28.295 32.578,28.083
no net on Top Overlay "TOPOVERLAY196" (solid, pour order 0): 90 vertices, not listed, extent 40.945,67.5 42.842,70.53
no net on Top Overlay "TOPOVERLAY195" (solid, pour order 0): 87 vertices, not listed, extent 73.931,68.3 75.727,70.53
no net on Top Overlay "TOPOVERLAY194" (solid, pour order 0): 97 vertices, not listed, extent 58.522,68.24 60.422,71.324
no net on Top Overlay "TOPOVERLAY193" (solid, pour order 0): 70.575,70.905 70.575,71.255 70.956,71.255 70.956,70.905
no net on Top Overlay "TOPOVERLAY192" (solid, pour order 0): 197 vertices, not listed, extent 79.142,68.25 81.485,71.246
no net on Top Overlay "TOPOVERLAY191" (solid, pour order 0): 51 vertices, not listed, extent 30.445,68.3 31.779,70.471
no net on Top Overlay "TOPOVERLAY190" (solid, pour order 0): 176 vertices, not listed, extent 66.948,68.25 68.685,70.524
no net on Top Overlay "TOPOVERLAY189" (solid, pour order 0): 51 vertices, not listed, extent 45.613,68.3 46.947,70.471
no net on Top Overlay "TOPOVERLAY188" (solid, pour order 0): 159 vertices, not listed, extent 37.168,68.3 40.308,70.53
no net on Top Overlay "TOPOVERLAY187" (solid, pour order 0): 51 vertices, not listed, extent 53.445,68.3 54.779,70.471
no net on Top Overlay "TOPOVERLAY186" (solid, pour order 0): 26.599,68.3 25.681,70.471 26.046,70.471 26.743,68.775 27.433,70.471 27.786,70.471 26.861,68.3
no net on Top Overlay "TOPOVERLAY185" (solid, pour order 0): 153 vertices, not listed, extent 54.911,68.25 56.86,70.53
no net on Top Overlay "TOPOVERLAY184" (solid, pour order 0): 153 vertices, not listed, extent 43.182,68.25 45.132,70.53
no net on Top Overlay "TOPOVERLAY183" (solid, pour order 0): 153 vertices, not listed, extent 64.677,68.25 66.626,70.53
no net on Top Overlay "TOPOVERLAY182" (solid, pour order 0): 153 vertices, not listed, extent 60.915,68.25 62.865,70.53
no net on Top Overlay "TOPOVERLAY181" (solid, pour order 0): 117 vertices, not listed, extent 71.434,68.24 73.437,70.53
no net on Top Overlay "TOPOVERLAY180" (solid, pour order 0): 123 vertices, not listed, extent 22.8,68.24 25.443,71.255
no net on Top Overlay "TOPOVERLAY179" (solid, pour order 0): 153 vertices, not listed, extent 34.738,68.25 36.687,70.53
no net on Top Overlay "TOPOVERLAY178" (solid, pour order 0): 153 vertices, not listed, extent 28.014,68.25 29.964,70.53
no net on Top Overlay "TOPOVERLAY177" (solid, pour order 0): 70.597,68.3 70.597,70.471 70.938,70.471 70.938,68.3
no net on Top Overlay "TOPOVERLAY176" (solid, pour order 0): 162 vertices, not listed, extent 47.072,68.24 48.884,70.521
no net on Top Overlay "TOPOVERLAY175" (solid, pour order 0): 86 vertices, not listed, extent 50.996,68.24 52.792,70.471
no net on Top Overlay "TOPOVERLAY174" (solid, pour order 0): 77.611,68.3 77.611,68.565 77.989,68.565 77.989,70.927 77.611,70.927 77.611,71.196 78.726,71.196 78.726,70.927 78.348,70.927 78.348,68.565 78.726,68.565 78.726,68.3
no net on Top Overlay "TOPOVERLAY173" (solid, pour order 0): 72 vertices, not listed, extent 49.287,68.259 50.634,71.096
no net on Top Overlay "TOPOVERLAY172" (solid, pour order 0): 72 vertices, not listed, extent 33.172,68.259 34.519,71.096
no net on Top Overlay "TOPOVERLAY171" (solid, pour order 0): 72 vertices, not listed, extent 68.869,68.259 70.216,71.096
no net on Top Overlay "TOPOVERLAY170" (solid, pour order 0): 72 vertices, not listed, extent 63.112,68.259 64.458,71.096
no net on Top Overlay "TOPOVERLAY169" (solid, pour order 0): 90 vertices, not listed, extent 28.626,34.2 29.384,35.412
no net on Top Overlay "TOPOVERLAY168" (solid, pour order 0): 23.788,34.52 23.527,35.388 23.668,35.388 23.856,34.735 24.094,35.388 24.197,35.388 24.426,34.735 24.612,35.388 24.747,35.388 24.481,34.52 24.383,34.52 24.142,35.194 23.886,34.52
no net on Top Overlay "TOPOVERLAY167" (solid, pour order 0): 51 vertices, not listed, extent 25.833,34.52 26.366,35.388
no net on Top Overlay "TOPOVERLAY166" (solid, pour order 0): 87 vertices, not listed, extent 27.652,34.52 28.371,35.412
no net on Top Overlay "TOPOVERLAY165" (solid, pour order 0): 72 vertices, not listed, extent 30.464,34.504 31.003,35.638
no net on Top Overlay "TOPOVERLAY164" (solid, pour order 0): 153 vertices, not listed, extent 24.86,34.5 25.64,35.412
no net on Top Overlay "TOPOVERLAY163" (solid, pour order 0): 117 vertices, not listed, extent 22.614,34.496 23.415,35.412
no net on Top Overlay "TOPOVERLAY162" (solid, pour order 0): 86 vertices, not listed, extent 29.578,34.496 30.297,35.388
no net on Top Overlay "TOPOVERLAY161" (solid, pour order 0): 26.981,34.52 26.981,34.626 27.132,34.626 27.132,35.571 26.981,35.571 26.981,35.678 27.427,35.678 27.427,35.571 27.276,35.571 27.276,34.626 27.427,34.626 27.427,34.52
no net on Top Overlay "TOPOVERLAY160" (solid, pour order 0): 65 vertices, not listed, extent 21.75,34.52 22.509,35.678
no net on Top Overlay "TOPOVERLAY159" (solid, pour order 0): 101.193,37.445 101.193,37.706 101.454,37.706 101.454,37.445
no net on Top Overlay "TOPOVERLAY158" (solid, pour order 0): 95.704,40.843 95.704,41.104 95.965,41.104 95.965,40.843
no net on Top Overlay "TOPOVERLAY157" (solid, pour order 0): 95.442,31.171 95.442,31.432 95.704,31.432 95.704,31.171
no net on Top Overlay "TOPOVERLAY156" (solid, pour order 0): 90.998,39.536 90.998,39.797 91.26,39.797 91.26,39.536
no net on Top Overlay "TOPOVERLAY155" (solid, pour order 0): 99.363,30.91 99.363,31.171 99.625,31.171 99.625,30.91
no net on Top Overlay "TOPOVERLAY154" (solid, pour order 0): 94.135,35.876 94.135,36.138 94.396,36.138 94.396,35.876
no net on Top Overlay "TOPOVERLAY153" (solid, pour order 0): 95.442,28.296 95.442,28.557 95.704,28.557 95.704,28.818 95.965,28.818 95.965,28.296
no net on Top Overlay "TOPOVERLAY152" (solid, pour order 0): 98.579,29.864 98.579,30.125 98.84,30.125 98.84,29.864
no net on Top Overlay "TOPOVERLAY151" (solid, pour order 0): 93.874,38.229 93.874,38.49 94.396,38.49 94.396,38.229
no net on Top Overlay "TOPOVERLAY150" (solid, pour order 0): 97.272,35.615 97.272,35.876 97.533,35.876 97.533,35.615
no net on Top Overlay "TOPOVERLAY149" (solid, pour order 0): 90.737,28.818 90.737,29.341 91.26,29.341 91.26,29.08 90.998,29.08 90.998,28.818
no net on Top Overlay "TOPOVERLAY148" (solid, pour order 0): 94.396,40.582 94.396,40.843 94.658,40.843 94.658,40.582
no net on Top Overlay "TOPOVERLAY147" (solid, pour order 0): 99.363,37.445 99.363,37.706 99.625,37.706 99.625,37.445
no net on Top Overlay "TOPOVERLAY146" (solid, pour order 0): 90.214,34.569 90.214,34.831 90.475,34.831 90.475,34.569
no net on Top Overlay "TOPOVERLAY145" (solid, pour order 0): 96.749,38.752 96.749,39.013 97.011,39.013 97.011,38.752
no net on Top Overlay "TOPOVERLAY144" (solid, pour order 0): 96.488,39.013 96.488,39.797 96.749,39.797 96.749,39.013
no net on Top Overlay "TOPOVERLAY143" (solid, pour order 0): 93.612,31.694 93.612,31.955 93.874,31.955 93.874,31.694
no net on Top Overlay "TOPOVERLAY142" (solid, pour order 0): 97.272,32.478 97.272,32.739 97.533,32.739 97.533,32.478
no net on Top Overlay "TOPOVERLAY141" (solid, pour order 0): 97.533,38.229 97.533,38.49 97.795,38.49 97.795,38.229
no net on Top Overlay "TOPOVERLAY140" (solid, pour order 0): 88.646,31.955 88.646,32.217 89.168,32.217 89.168,31.955
no net on Top Overlay "TOPOVERLAY139" (solid, pour order 0): 91.782,35.092 91.782,35.354 92.044,35.354 92.044,35.092
no net on Top Overlay "TOPOVERLAY138" (solid, pour order 0): 90.737,40.582 90.737,41.104 91.26,41.104 91.26,40.843 90.998,40.843 90.998,40.582
no net on Top Overlay "TOPOVERLAY137" (solid, pour order 0): 96.749,28.296 96.749,28.557 97.011,28.557 97.011,28.296
no net on Top Overlay "TOPOVERLAY136" (solid, pour order 0): 88.907,35.876 88.907,36.138 89.168,36.138 89.168,35.876
no net on Top Overlay "TOPOVERLAY135" (solid, pour order 0): 100.409,38.49 100.409,39.013 100.67,39.013 100.67,38.49
no net on Top Overlay "TOPOVERLAY134" (solid, pour order 0): 89.168,31.694 89.168,31.955 89.43,31.955 89.43,31.694
no net on Top Overlay "TOPOVERLAY133" (solid, pour order 0): 89.691,35.876 89.691,36.661 89.953,36.661 89.953,35.876
no net on Top Overlay "TOPOVERLAY132" (solid, pour order 0): 91.782,40.32 91.782,40.582 92.044,40.582 92.044,40.32
no net on Top Overlay "TOPOVERLAY131" (solid, pour order 0): 89.168,33.785 89.168,34.046 89.43,34.046 89.43,33.785
no net on Top Overlay "TOPOVERLAY130" (solid, pour order 0): 95.965,33.262 95.965,33.524 96.488,33.524 96.488,33.262
no net on Top Overlay "TOPOVERLAY129" (solid, pour order 0): 91.782,31.171 91.782,31.432 92.044,31.432 92.044,31.171
no net on Top Overlay "TOPOVERLAY128" (solid, pour order 0): 90.214,35.615 90.214,35.876 90.475,35.876 90.475,35.615
no net on Top Overlay "TOPOVERLAY127" (solid, pour order 0): 97.533,39.275 97.533,39.536 97.795,39.536 97.795,39.275
no net on Top Overlay "TOPOVERLAY126" (solid, pour order 0): 94.919,39.275 94.919,39.536 95.181,39.536 95.181,39.275
no net on Top Overlay "TOPOVERLAY125" (solid, pour order 0): 100.147,39.797 100.147,40.582 100.932,40.582 100.932,39.797
no net on Top Overlay "TOPOVERLAY124" (solid, pour order 0): 88.646,38.752 88.646,39.013 88.907,39.013 88.907,38.752
no net on Top Overlay "TOPOVERLAY123" (solid, pour order 0): 99.625,29.864 99.625,30.125 99.886,30.125 99.886,29.864
no net on Top Overlay "TOPOVERLAY122" (solid, pour order 0): 92.044,29.08 92.044,29.341 92.305,29.341 92.305,29.08
no net on Top Overlay "TOPOVERLAY121" (solid, pour order 0): 91.26,39.275 91.26,39.536 91.521,39.536 91.521,39.275
no net on Top Overlay "TOPOVERLAY120" (solid, pour order 0): 97.795,32.217 97.795,32.739 98.056,32.739 98.056,32.217
no net on Top Overlay "TOPOVERLAY119" (solid, pour order 0): 88.646,31.171 88.646,31.432 88.907,31.432 88.907,31.171
no net on Top Overlay "TOPOVERLAY118" (solid, pour order 0): 90.737,28.296 90.737,28.557 90.998,28.557 90.998,28.296
no net on Top Overlay "TOPOVERLAY117" (solid, pour order 0): 88.907,35.092 88.907,35.354 88.646,35.354 88.646,35.615 89.168,35.615 89.168,35.092
no net on Top Overlay "TOPOVERLAY116" (solid, pour order 0): 89.168,39.797 89.168,40.582 89.953,40.582 89.953,39.797
no net on Top Overlay "TOPOVERLAY115" (solid, pour order 0): 100.932,33.001 100.932,33.262 101.193,33.262 101.193,33.524 101.454,33.524 101.454,33.001
no net on Top Overlay "TOPOVERLAY114" (solid, pour order 0): 93.089,37.968 93.089,38.49 93.351,38.49 93.351,38.229 93.612,38.229 93.612,37.968
no net on Top Overlay "TOPOVERLAY113" (solid, pour order 0): 97.272,37.445 97.272,37.706 97.533,37.706 97.533,37.445
no net on Top Overlay "TOPOVERLAY112" (solid, pour order 0): 93.351,29.08 93.351,29.341 93.612,29.341 93.612,29.08
no net on Top Overlay "TOPOVERLAY111" (solid, pour order 0): 88.646,34.046 88.646,34.308 88.907,34.308 88.907,34.569 89.168,34.569 89.168,34.046
no net on Top Overlay "TOPOVERLAY110" (solid, pour order 0): 91.521,32.217 91.521,32.478 91.782,32.478 91.782,32.217
no net on Top Overlay "TOPOVERLAY109" (solid, pour order 0): 97.533,40.582 97.533,40.843 97.795,40.843 97.795,40.582
no net on Top Overlay "TOPOVERLAY108" (solid, pour order 0): 97.011,38.49 97.011,38.752 97.272,38.752 97.272,38.49
no net on Top Overlay "TOPOVERLAY107" (solid, pour order 0): 90.214,31.432 90.214,31.694 90.475,31.694 90.475,31.432
no net on Top Overlay "TOPOVERLAY106" (solid, pour order 0): 90.214,36.138 90.214,36.399 90.475,36.399 90.475,36.138
no net on Top Overlay "TOPOVERLAY105" (solid, pour order 0): 94.396,31.171 94.396,31.694 94.135,31.694 94.135,31.955 94.396,31.955 94.396,32.217 94.658,32.217 94.658,31.955 94.919,31.955 94.919,31.694 94.658,31.694 94.658,31.171
no net on Top Overlay "TOPOVERLAY104" (solid, pour order 0): 88.646,34.831 88.646,35.092 88.907,35.092 88.907,34.831
no net on Top Overlay "TOPOVERLAY103" (solid, pour order 0): 93.089,31.694 93.089,32.217 93.351,32.217 93.351,31.694
no net on Top Overlay "TOPOVERLAY102" (solid, pour order 0): 95.181,40.32 95.181,40.582 94.919,40.582 94.919,40.843 95.181,40.843 95.181,41.104 95.442,41.104 95.442,40.32
no net on Top Overlay "TOPOVERLAY101" (solid, pour order 0): 98.318,38.49 98.318,38.752 98.579,38.752 98.579,38.49
no net on Top Overlay "TOPOVERLAY100" (solid, pour order 0): 96.226,40.059 96.226,40.582 95.965,40.582 95.965,40.843 96.226,40.843 96.226,41.104 96.749,41.104 96.749,40.32 96.488,40.32 96.488,40.059
no net on Top Overlay "TOPOVERLAY99" (solid, pour order 0): 91.782,40.843 91.782,41.104 92.044,41.104 92.044,40.843
no net on Top Overlay "TOPOVERLAY98" (solid, pour order 0): 97.795,35.615 97.795,35.876 98.056,35.876 98.056,35.615
no net on Top Overlay "TOPOVERLAY97" (solid, pour order 0): 88.646,28.296 88.646,30.125 90.475,30.125 90.475,28.296
no net on Top Overlay "TOPOVERLAY96" (solid, pour order 0): 100.67,33.524 100.67,33.785 100.932,33.785 100.932,33.524
no net on Top Overlay "TOPOVERLAY95" (solid, pour order 0): 90.737,40.059 90.737,40.32 90.998,40.32 90.998,40.582 91.521,40.582 91.521,40.059
no net on Top Overlay "TOPOVERLAY94" (solid, pour order 0): 92.305,31.171 92.305,31.432 92.567,31.432 92.567,31.171
no net on Top Overlay "TOPOVERLAY93" (solid, pour order 0): 88.907,36.399 88.907,36.661 89.168,36.661 89.168,36.399
no net on Top Overlay "TOPOVERLAY92" (solid, pour order 0): 88.646,36.661 88.646,36.922 88.907,36.922 88.907,36.661
no net on Top Overlay "TOPOVERLAY91" (solid, pour order 0): 94.919,29.864 94.919,30.125 95.181,30.125 95.181,29.864
no net on Top Overlay "TOPOVERLAY90" (solid, pour order 0): 96.749,31.171 96.749,31.432 96.226,31.432 96.226,31.955 96.488,31.955 96.488,32.739 96.749,32.739 96.749,31.694 97.011,31.694 97.011,31.432 97.533,31.432 97.533,31.171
